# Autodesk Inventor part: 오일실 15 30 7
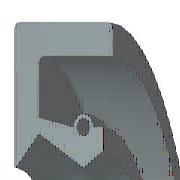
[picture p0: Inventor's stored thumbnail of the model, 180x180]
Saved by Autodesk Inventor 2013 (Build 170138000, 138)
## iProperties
IsCustomPart: 1
Created: 2012-02
Part Number: 오일실 15 30 7
Material: 고무
Description: 오일-실
Document SubType Name: Modeling
Standard: KS B 2804
Designer: mduedu
Standards Organization: KS
Language: ko-KR
Size Designation: D - 15 30 7
Categories: <MemberInstance><Categories><Category DisplayName="샤프트 부품" InternalName="7f7aeb1f-a693-4053-b835-cee3144e0d98" Mnemonic="SHFT"><Category DisplayName="실링" Intern
Density: 0.93 g/cm^3
Author: mduedu
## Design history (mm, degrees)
revolve "본체" stored, may be unused: angle "d17" = 90 deg
revolve "스프링1" stored, may be unused: angle "d18" = 90 deg
body "Solid1"
sketch "스케치1"
  geometry: L1 (0, 15)-(7, 15); L2 (7, 13.25)-(1.75, 13.25); L3 (1.75, 9.25)-(4.9, 7.5); L4 (4.9, 7.5)-(0, 7.5); L5 (0, 0)-(9.586, 0) reference; L6 (4.9, 7.5)-(6.3, 8.375); L7 (0, 18)-(0, -3) reference; L8 (-1.941, 0)-(11.507, 0) reference; L9 (4.2, 9.6)-(1.75, 10.09); L10 (1.75, 10.09)-(1.75, 13.25); L11 (0, 15)-(0, 7.588); L12 (4.9, 7.5)-(0, 7.5); L13 (1.75, 9.25)-(0.152, 7.528); L14 (7, 15)-(7, 13.25); L15 (5.6, 9.6)-(6.3, 9.6); L16 (6.3, 9.6)-(6.3, 8.375); C1 r 0.455 at (4.9, 9.6); A1 r 0.7 centre (4.9, 9.6) between (5.6, 9.6) and (4.2, 9.6); A2 r 0.088 centre (0.088, 7.588) between (0, 7.588) and (0.152, 7.528); 1 further point
  constraints: 28 end point, 5 horizontal alignment, 5 point on line, 4 point on circle, 4 vertical alignment, 3 centre point, 3 tangent, 2 collinear, 2 horizontal, 2 perpendicular, 1 coincident, 1 parallel
  dimensions: "d0" = 30 diameter of L1 L5 (= SD2); "d1" = 1.75 distance of L1.end L2.start (= SD); "d2" = 0.91 diameter of C1 (= SPDI); "d3" = 1.4 diameter of A1 (= SPDA); "d4" = 15 diameter of L3.end L5 (= NND); "d5" = 18.5 diameter of L3.start L5 (= TKDM); "d7" = 20.18 diameter of L9.end L5 (= TKDM + 0.24 x SWDT); "d8" = 1.75 distance between parallel lines of L11 L10 (= SD); "d9" = 4.9 distance from line of L11 C1.centre (= SPDST); "d10" = 19.2 diameter of C1.centre L5 (= HLDM); "d11" = 0.0875 radius of A2 (= 0.25 x LAB); "d12" = 6.3 distance between parallel lines of L11 L16 (= SDI); "d13" = 16.75 diameter of L6.end L5 (= ABDM); "d14" = 7 distance from line of L11 L1.end (= SWDT)
fillet "모깎기1" dims "d6" = 0.3 (= RR)
other parameters: "SD2" = 30 [user parameter; used in 1 equation term], "SWDT" = 7 [user parameter; used in 2 equation terms], "RR" = 0.3 [user parameter; used in 1 equation term], "SD" = 1.75 [user parameter; used in 2 equation terms], "NND" = 15 [user parameter; used in 1 equation term], "SPDA" = 1.4 [user parameter; used in 1 equation term], "SPDI" = 0.91 [user parameter; used in 1 equation term], "TKDM" = 18.5 [user parameter; used in 2 equation terms], "HLDM" = 19.2 [user parameter; used in 1 equation term], "ABDM" = 16.75 [user parameter; used in 1 equation term], "SDI" = 6.3 [user parameter; used in 1 equation term], "SPDST" = 4.9 [user parameter; used in 1 equation term], "LAB" = 0.35 [user parameter; used in 1 equation term], "d15" = 0, "d16" = 0, "d19" = 0
